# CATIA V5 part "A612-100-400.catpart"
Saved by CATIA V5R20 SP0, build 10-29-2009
Part number: A612-100-400
Source: Unknown
Property "A": "30.000"
Property "ARTICLENO": "A612-100-400"
Property "B": "40.000"
Property "BOMINFO": "A612-100-400"
Property "CODE": "A612-100-400"
Property "D": "17.500"
Property "FORM": "C"
Property "L": "400.000"
Property "L1": "45.000"
Property "L2": "80.000"
Property "L3": "75.000"
Property "LINA": "A612-100-400"
Property "NB": "A612-100-400"
Property "NBSYN": "$CODE."
Property "NN": "A612"
Property "NT": "CDI 3357 E-Type Wear Plates, steel and self-lubricating"
Property "SUPPLIER": "CF"
Property "T": "25.000"
Property "W": "100.000"
Bounding box of the stored display mesh (mm): x 0 to 25, y 0 to 400, z 0 to 100
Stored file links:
  C:\Users\Utente\Desktop\3D files A612\A612-100-400.catpart
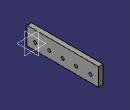
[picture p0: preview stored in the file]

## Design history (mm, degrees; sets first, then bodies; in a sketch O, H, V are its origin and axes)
Body1 "Geometry.1" (main body)
  Solid1 "A612-100-400.catpart": solid without history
